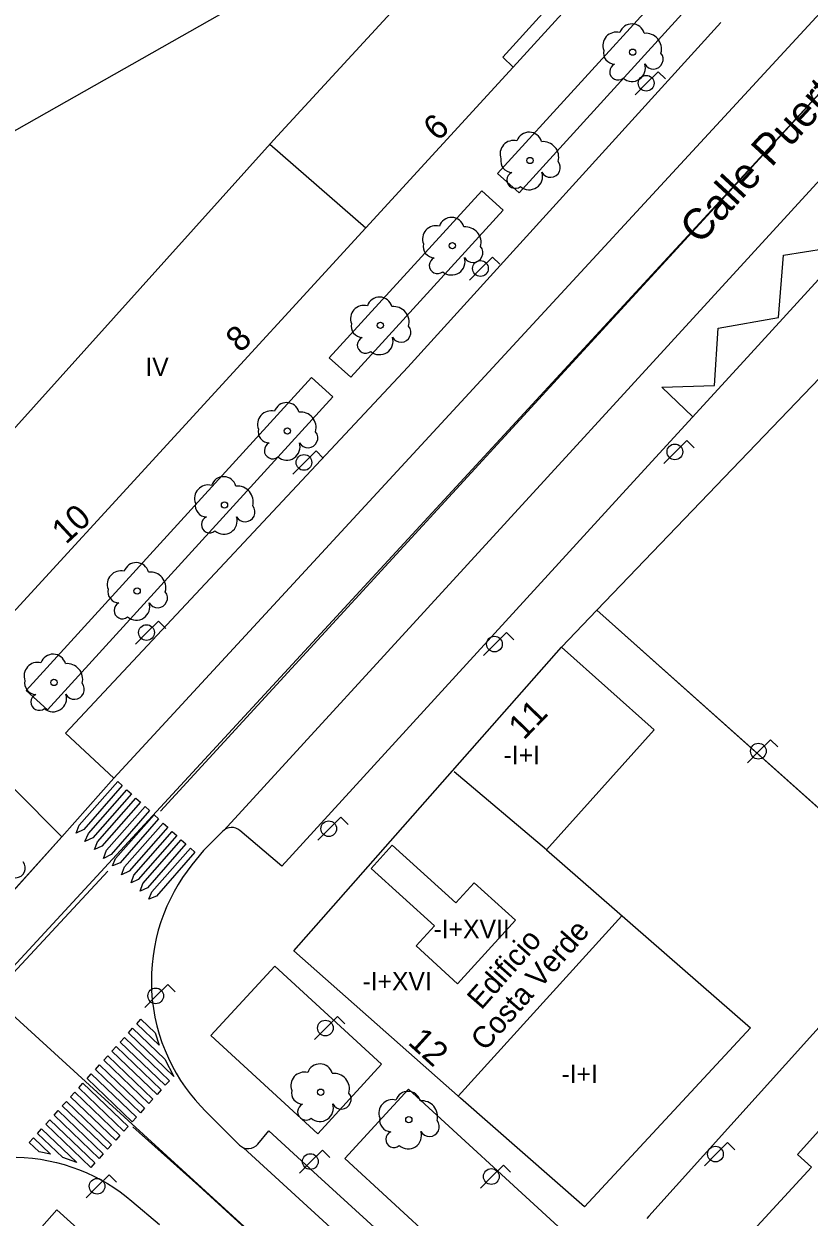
# Model space of a CAD drawing. Extents: x 282771 to 285132, y 4823109 to 4825496.
# Drawn here: x 283832.1 to 283895.8, y 4823389.4 to 4823486.3 of the extents above; entities that cross this region are included whole.
import ezdxf

# ---------------------------------------------------------------- set-up
doc = ezdxf.new("R2010")
doc.units = 0
for name, color, linetype in [('ACERA-BORDILLO', 7, 'Continuous'), ('ACERA-INTERIOR', 7, 'Continuous'), ('ARBOL', 7, 'Continuous'), ('CALLE-EJE', 7, 'Continuous'), ('CALLE-TEXTO', 7, 'Continuous'), ('CARGA_DESCARGA', 7, 'Continuous'), ('EDIFICIO', 7, 'Continuous'), ('FAROLA', 7, 'Continuous'), ('MEDIANERA', 7, 'Continuous'), ('NUM-LOCAL', 7, 'Continuous'), ('NUM-PORTAL', 7, 'Continuous'), ('PASO-PEATONES', 7, 'Continuous'), ('SENAL-VIARIA', 7, 'Continuous'), ('TXT-ALTURA-EDIFICIO', 7, 'Continuous'), ('TXT-EDIFICIOS', 7, 'Continuous'), ('ZONA-VERDE', 7, 'Continuous')]:
    doc.layers.add(name, color=color, linetype=linetype)

msp = doc.modelspace()

# ---------------------------------------------------------------- linework, layer by layer
at = {"layer": 'ACERA-BORDILLO'}
for points in [[(283785.072, 4823373.561), (283808.693, 4823399.156), (283812.812, 4823395.481), (283835.171, 4823420.3), (283839.411, 4823425.06), (283835.471, 4823428.73), (283863.261, 4823458.42), (283888.661, 4823486.42)], [(283908.741, 4823478.83), (283891.081, 4823459.53), (283880.401, 4823447.87), (283853.041, 4823417.91), (283849.616, 4823420.825), (283849.474, 4823420.926), (283849.307, 4823421.004), (283849.122, 4823421.051), (283848.928, 4823421.062), (283848.735, 4823421.036), (283848.555, 4823420.974), (283848.395, 4823420.882), (283848.261, 4823420.77), (283846.671, 4823419.18), (283845.739, 4823418.017), (283845.355, 4823417.516), (283844.986, 4823416.991), (283844.636, 4823416.444), (283844.306, 4823415.874), (283843.997, 4823415.282), (283843.712, 4823414.67), (283843.451, 4823414.039), (283843.218, 4823413.39), (283843.013, 4823412.726), (283842.838, 4823412.047), (283842.694, 4823411.356), (283842.582, 4823410.655), (283842.503, 4823409.947), (283842.457, 4823409.233), (283842.446, 4823408.516), (283842.469, 4823407.799), (283842.526, 4823407.083), (283842.618, 4823406.372), (283842.742, 4823405.667), (283842.9, 4823404.972), (283843.09, 4823404.288), (283843.31, 4823403.618), (283843.56, 4823402.963), (283843.838, 4823402.326), (283844.143, 4823401.707), (283844.472, 4823401.109), (283844.824, 4823400.533), (283845.197, 4823399.979), (283845.589, 4823399.45), (283845.998, 4823398.945), (283846.423, 4823398.465), (283846.86, 4823398.01), (283849.604, 4823395.278), (283849.752, 4823395.157), (283849.932, 4823395.061), (283850.137, 4823395.001), (283850.356, 4823394.988), (283850.572, 4823395.022), (283850.771, 4823395.099), (283850.941, 4823395.212), (283851.077, 4823395.346), (283851.981, 4823396.431), (283855.311, 4823393.371), (283891.081, 4823360.721)], [(283831.469, 4823394.303), (283832.135, 4823394.274), (283832.797, 4823394.215), (283833.456, 4823394.127), (283834.107, 4823394.011), (283834.751, 4823393.866), (283835.384, 4823393.694), (283836.006, 4823393.496), (283836.614, 4823393.273), (283837.208, 4823393.026), (283837.785, 4823392.755), (283838.346, 4823392.464), (283838.888, 4823392.152), (283839.411, 4823391.822), (283839.914, 4823391.475), (283839.914, 4823391.475), (283839.914, 4823391.475), (283839.914, 4823391.475), (283839.914, 4823391.475), (283840.396, 4823391.112), (283840.857, 4823390.736), (283843.105, 4823388.825)]]:
    msp.add_lwpolyline(points, dxfattribs=at)
at = {"layer": 'ACERA-INTERIOR'}
msp.add_line((283878.605, 4823438.71), (283875.731, 4823435.71), dxfattribs=at)
msp.add_lwpolyline([(283895.671, 4823509), (283891.081, 4823503.96), (283885.131, 4823497.43), (283871.801, 4823482.79)], dxfattribs=at)
at = {"layer": 'ARBOL'}
for centre in [(283881.511, 4823484), (283873.172, 4823475.208), (283866.875, 4823468.287), (283861.033, 4823461.82), (283853.488, 4823453.255), (283848.383, 4823447.242), (283841.292, 4823440.265), (283834.542, 4823432.834), (283856.191, 4823399.571), (283863.341, 4823397.341)]:
    msp.add_circle(centre, 0.255, dxfattribs=at)
for centre, radius, start, end in [((283880.181, 4823484.53), 1.097, 75.4318, 200.55608), ((283881.441, 4823485.26), 1.038, 15.64228, 161.38435), ((283882.571, 4823484.26), 1.272, 345.03273, 95.79925), ((283880.071, 4823483.96), 0.935, 168.59898, 268.13236), ((283883.181, 4823483.43), 0.797, 208.96246, 38.99103), ((283880.311, 4823482.41), 0.672, 113.73672, 309.4725), ((283881.451, 4823482.71), 1.086, 228.95447, 17.92796), ((283871.842, 4823475.738), 1.097, 75.4318, 200.55608), ((283873.102, 4823476.468), 1.038, 15.64228, 161.38435), ((283874.232, 4823475.468), 1.272, 345.03273, 95.79925), ((283871.732, 4823475.168), 0.935, 168.59898, 268.13236), ((283874.842, 4823474.638), 0.797, 208.96246, 38.99103), ((283871.972, 4823473.618), 0.672, 113.73672, 309.4725), ((283873.112, 4823473.918), 1.086, 228.95447, 17.92796), ((283866.805, 4823469.547), 1.038, 15.64228, 161.38435), ((283865.545, 4823468.817), 1.097, 75.4318, 200.55608), ((283867.935, 4823468.547), 1.272, 345.03273, 95.79925), ((283865.435, 4823468.247), 0.935, 168.59898, 268.13236), ((283868.545, 4823467.717), 0.797, 208.96246, 38.99103), ((283865.675, 4823466.697), 0.672, 113.73672, 309.4725), ((283866.815, 4823466.997), 1.086, 228.95447, 17.92796), ((283859.703, 4823462.35), 1.097, 75.4318, 200.55608), ((283860.963, 4823463.08), 1.038, 15.64228, 161.38435), ((283862.093, 4823462.08), 1.272, 345.03273, 95.79925), ((283859.593, 4823461.78), 0.935, 168.59898, 268.13236), ((283862.703, 4823461.25), 0.797, 208.96246, 38.99103), ((283859.833, 4823460.23), 0.672, 113.73672, 309.4725), ((283860.973, 4823460.53), 1.086, 228.95447, 17.92796), ((283853.418, 4823454.515), 1.038, 15.64228, 161.38435), ((283852.158, 4823453.785), 1.097, 75.4318, 200.55608), ((283854.548, 4823453.515), 1.272, 345.03273, 95.79925), ((283852.048, 4823453.215), 0.935, 168.59898, 268.13236), ((283855.158, 4823452.685), 0.797, 208.96246, 38.99103), ((283852.288, 4823451.665), 0.672, 113.73672, 309.4725), ((283853.428, 4823451.965), 1.086, 228.95447, 17.92796), ((283847.053, 4823447.772), 1.097, 75.4318, 200.55608), ((283848.313, 4823448.502), 1.038, 15.64228, 161.38435), ((283849.443, 4823447.502), 1.272, 345.03273, 95.79925), ((283846.943, 4823447.202), 0.935, 168.59898, 268.13236), ((283850.053, 4823446.672), 0.797, 208.96246, 38.99103), ((283847.183, 4823445.652), 0.672, 113.73672, 309.4725), ((283848.323, 4823445.952), 1.086, 228.95447, 17.92796), ((283839.962, 4823440.795), 1.097, 75.4318, 200.55608), ((283841.222, 4823441.525), 1.038, 15.64228, 161.38435), ((283842.352, 4823440.525), 1.272, 345.03273, 95.79925), ((283839.852, 4823440.225), 0.935, 168.59898, 268.13236), ((283842.962, 4823439.695), 0.797, 208.96246, 38.99103), ((283840.092, 4823438.675), 0.672, 113.73672, 309.4725), ((283841.232, 4823438.975), 1.086, 228.95447, 17.92796), ((283834.472, 4823434.094), 1.038, 15.64228, 161.38435), ((283833.212, 4823433.364), 1.097, 75.4318, 200.55608), ((283835.602, 4823433.094), 1.272, 345.03273, 95.79925), ((283833.102, 4823432.794), 0.935, 168.59898, 268.13236), ((283836.212, 4823432.264), 0.797, 208.96246, 38.99103), ((283833.342, 4823431.244), 0.672, 113.73672, 309.4725), ((283834.482, 4823431.544), 1.086, 228.95447, 17.92796), ((283831.429, 4823417.776), 0.797, 208.96246, 38.99103), ((283854.861, 4823400.101), 1.097, 75.4318, 200.55608), ((283856.121, 4823400.831), 1.038, 15.64228, 161.38435), ((283857.251, 4823399.831), 1.272, 345.03273, 95.79925), ((283854.751, 4823399.531), 0.935, 168.59898, 268.13236), ((283857.861, 4823399.001), 0.797, 208.96246, 38.99103), ((283863.271, 4823398.601), 1.038, 15.64228, 161.38435), ((283854.991, 4823397.981), 0.672, 113.73672, 309.4725), ((283856.131, 4823398.281), 1.086, 228.95447, 17.92796), ((283862.011, 4823397.871), 1.097, 75.4318, 200.55608), ((283864.401, 4823397.601), 1.272, 345.03273, 95.79925), ((283861.901, 4823397.301), 0.935, 168.59898, 268.13236), ((283862.141, 4823395.751), 0.672, 113.73672, 309.4725), ((283863.281, 4823396.051), 1.086, 228.95447, 17.92796), ((283865.011, 4823396.771), 0.797, 208.96246, 38.99103)]:
    msp.add_arc(centre, radius, start, end, dxfattribs=at)
at = {"layer": 'CALLE-EJE'}
for points in [[(283915.67, 4823562.869), (283930.947, 4823535.839), (283932.069, 4823532.819), (283932.63, 4823529.669), (283932.738, 4823527.699), (283932.738, 4823525.68), (283932.366, 4823523.289), (283931.782, 4823521.004), (283930.796, 4823518.998), (283923.914, 4823510.21), (283829.231, 4823407.601)], [(283918.081, 4823326.402), (283829.231, 4823407.601)]]:
    msp.add_lwpolyline(points, dxfattribs=at)
at = {"layer": 'CARGA_DESCARGA'}
msp.add_lwpolyline([(283886.377, 4823454.394), (283883.876, 4823456.809), (283888.139, 4823456.939), (283888.44, 4823461.604), (283893.338, 4823462.459), (283893.736, 4823467.519), (283898.863, 4823468.329), (283899.318, 4823473.401), (283901.842, 4823471.291)], dxfattribs=at)
at = {"layer": 'EDIFICIO'}
for points in [[(283832.841, 4823490.48), (283870.601, 4823511.93), (283880.631, 4823494.27), (283870.961, 4823483.59), (283871.801, 4823482.79), (283859.851, 4823469.75), (283829.381, 4823436.52), (283822.051, 4823443.15), (283852.351, 4823476.86), (283871.091, 4823497.24), (283869.751, 4823499.39), (283829.221, 4823476.43), (283823.881, 4823485.39), (283832.841, 4823490.48)], [(283875.731, 4823435.71), (283883.251, 4823428.98), (283874.501, 4823419.25), (283891.061, 4823404.801), (283877.591, 4823390.271), (283867.541, 4823399.091), (283854.011, 4823411.051), (283875.731, 4823435.71)]]:
    msp.add_lwpolyline(points, dxfattribs=at)
at = {"layer": 'FAROLA'}
for p, q in [((283883.58, 4823482.414), (283882.64, 4823481.484)), ((283884.17, 4823481.824), (283883.58, 4823482.414)), ((283882.64, 4823481.484), (283881.71, 4823480.544)), ((283870.134, 4823467.37), (283869.194, 4823466.44)), ((283870.724, 4823466.78), (283870.134, 4823467.37)), ((283869.194, 4823466.44), (283868.264, 4823465.5)), ((283855.81, 4823451.625), (283854.87, 4823450.695)), ((283856.4, 4823451.035), (283855.81, 4823451.625)), ((283884.971, 4823451.553), (283884.041, 4823450.613)), ((283885.911, 4823452.483), (283884.971, 4823451.553)), ((283886.501, 4823451.893), (283885.911, 4823452.483)), ((283854.87, 4823450.695), (283853.94, 4823449.755)), ((283843.034, 4823437.814), (283842.094, 4823436.884)), ((283843.624, 4823437.224), (283843.034, 4823437.814)), ((283842.094, 4823436.884), (283841.164, 4823435.944)), ((283871.269, 4823436.882), (283870.329, 4823435.952)), ((283871.859, 4823436.292), (283871.269, 4823436.882)), ((283870.329, 4823435.952), (283869.399, 4823435.012)), ((283892.686, 4823428.186), (283891.746, 4823427.256)), ((283893.276, 4823427.596), (283892.686, 4823428.186)), ((283891.746, 4823427.256), (283890.816, 4823426.316)), ((283857.822, 4823421.892), (283856.882, 4823420.962)), ((283858.412, 4823421.302), (283857.822, 4823421.892)), ((283856.882, 4823420.962), (283855.952, 4823420.022)), ((283843.781, 4823408.321), (283842.841, 4823407.391)), ((283844.371, 4823407.731), (283843.781, 4823408.321)), ((283842.841, 4823407.391), (283841.911, 4823406.451)), ((283857.548, 4823405.709), (283856.608, 4823404.779)), ((283858.138, 4823405.119), (283857.548, 4823405.709)), ((283856.608, 4823404.779), (283855.678, 4823403.839)), ((283889.202, 4823395.477), (283888.262, 4823394.547)), ((283889.792, 4823394.887), (283889.202, 4823395.477)), ((283856.329, 4823394.873), (283855.389, 4823393.943)), ((283856.919, 4823394.283), (283856.329, 4823394.873)), ((283888.262, 4823394.547), (283887.332, 4823393.607)), ((283855.389, 4823393.943), (283854.459, 4823393.003)), ((283871.014, 4823393.657), (283870.074, 4823392.727)), ((283871.604, 4823393.067), (283871.014, 4823393.657)), ((283839.025, 4823392.867), (283838.085, 4823391.937)), ((283839.615, 4823392.277), (283839.025, 4823392.867)), ((283870.074, 4823392.727), (283869.144, 4823391.787)), ((283838.085, 4823391.937), (283837.155, 4823390.997))]:
    msp.add_line(p, q, dxfattribs=at)
for centre, radius in [((283882.6, 4823481.484), 0.637), ((283869.154, 4823466.44), 0.637), ((283884.931, 4823451.553), 0.637), ((283854.83, 4823450.695), 0.637), ((283842.054, 4823436.884), 0.638), ((283870.289, 4823435.952), 0.637), ((283891.706, 4823427.256), 0.638), ((283856.842, 4823420.962), 0.637), ((283842.801, 4823407.391), 0.637), ((283856.568, 4823404.779), 0.637), ((283855.349, 4823393.943), 0.637), ((283888.222, 4823394.547), 0.638), ((283838.045, 4823391.937), 0.637), ((283870.034, 4823392.727), 0.637)]:
    msp.add_circle(centre, radius, dxfattribs=at)
at = {"layer": 'MEDIANERA'}
for points in [[(283852.051, 4823476.53), (283859.851, 4823469.75)], [(283874.501, 4823419.25), (283867.021, 4823425.58)], [(283868.651, 4823416.581), (283867.161, 4823414.941), (283861.991, 4823419.63), (283860.281, 4823417.74), (283865.421, 4823413.081), (283863.931, 4823411.441), (283867.301, 4823408.381), (283872.001, 4823413.541), (283868.651, 4823416.581)], [(283880.631, 4823413.891), (283867.331, 4823399.261)]]:
    msp.add_lwpolyline(points, dxfattribs=at)
at = {"layer": 'PASO-PEATONES'}
for points in [[(283836.34, 4823420.603), (283836.598, 4823421.239), (283839.72, 4823424.8), (283840.091, 4823424.464), (283836.967, 4823420.9)], [(283837.054, 4823419.928), (283837.335, 4823420.562), (283840.457, 4823424.123), (283840.827, 4823423.787), (283837.703, 4823420.223)], [(283837.846, 4823419.265), (283838.071, 4823419.885), (283841.195, 4823423.449), (283841.564, 4823423.11), (283838.44, 4823419.546)], [(283838.56, 4823418.551), (283838.808, 4823419.208), (283841.932, 4823422.772), (283842.3, 4823422.434), (283839.176, 4823418.87)], [(283839.288, 4823417.954), (283839.544, 4823418.531), (283842.668, 4823422.095), (283843.037, 4823421.757), (283839.913, 4823418.193)], [(283840.015, 4823417.227), (283840.281, 4823417.855), (283843.405, 4823421.418), (283843.773, 4823421.08), (283840.649, 4823417.516)], [(283840.807, 4823416.565), (283841.017, 4823417.178), (283844.141, 4823420.742), (283844.51, 4823420.403), (283841.386, 4823416.839)], [(283841.547, 4823415.902), (283841.754, 4823416.501), (283844.878, 4823420.065), (283845.246, 4823419.726), (283842.122, 4823416.163)], [(283842.248, 4823415.253), (283842.491, 4823415.824), (283845.615, 4823419.388), (283845.983, 4823419.05), (283842.859, 4823415.486)], [(283843.074, 4823403.389), (283841.265, 4823405.127), (283841.601, 4823405.498), (283842.744, 4823404.399)], [(283844.279, 4823400.845), (283840.593, 4823404.386), (283840.929, 4823404.757), (283843.547, 4823402.242)], [(283842.909, 4823399.387), (283839.25, 4823402.902), (283839.586, 4823403.273), (283843.245, 4823399.758)], [(283843.581, 4823400.129), (283839.922, 4823403.644), (283840.258, 4823404.015), (283843.916, 4823400.5)], [(283842.238, 4823398.646), (283838.579, 4823402.161), (283838.915, 4823402.532), (283842.573, 4823399.017)], [(283841.566, 4823397.904), (283837.907, 4823401.419), (283838.243, 4823401.79), (283841.902, 4823398.275)], [(283840.223, 4823396.421), (283836.564, 4823399.936), (283836.9, 4823400.307), (283840.559, 4823396.792)], [(283840.895, 4823397.163), (283837.236, 4823400.678), (283837.572, 4823401.049), (283841.23, 4823397.534)], [(283839.552, 4823395.68), (283835.893, 4823399.195), (283836.229, 4823399.565), (283839.887, 4823396.05)], [(283838.88, 4823394.938), (283835.221, 4823398.453), (283835.557, 4823398.824), (283839.216, 4823395.309)], [(283837.537, 4823393.455), (283833.878, 4823396.97), (283834.214, 4823397.341), (283837.873, 4823393.826)], [(283838.209, 4823394.196), (283834.55, 4823397.712), (283834.886, 4823398.082), (283838.544, 4823394.567)], [(283835.256, 4823394.26), (283833.207, 4823396.228), (283833.543, 4823396.599), (283836.394, 4823393.859)], [(283833.336, 4823394.718), (283832.535, 4823395.487), (283832.871, 4823395.857), (283834.251, 4823394.532)]]:
    msp.add_lwpolyline(points, close=True, dxfattribs=at)
at = {"layer": 'SENAL-VIARIA'}
for points in [[(283839.411, 4823425.06), (283920.682, 4823513.209)], [(283843.193, 4823422.375), (283923.682, 4823510.119)], [(283848.328, 4823420.826), (283927.419, 4823507.226)], [(283829.811, 4823407.712), (283838.929, 4823417.508)], [(283846.291, 4823391.979), (283840.943, 4823396.759)], [(283849.932, 4823395.061), (283905.341, 4823344.251)], [(283846.291, 4823391.979), (283899.822, 4823342.997)]]:
    msp.add_lwpolyline(points, dxfattribs=at)
at = {"layer": 'ZONA-VERDE'}
for p, q in [((283870.541, 4823474.162), (283883.752, 4823488.658)), ((283885.492, 4823487.088), (283872.281, 4823472.592)), ((283872.281, 4823472.592), (283870.541, 4823474.162)), ((283856.883, 4823459.176), (283869.255, 4823472.751)), ((283869.255, 4823472.751), (283870.995, 4823471.18)), ((283870.995, 4823471.18), (283858.624, 4823457.606)), ((283902.441, 4823463.59), (283878.605, 4823438.71)), ((283902.441, 4823463.59), (283878.605, 4823438.71)), ((283858.624, 4823457.606), (283856.883, 4823459.176)), ((283832.281, 4823432.18), (283855.44, 4823457.591)), ((283855.44, 4823457.591), (283857.18, 4823456.021)), ((283857.18, 4823456.021), (283834.021, 4823430.61)), ((283834.021, 4823430.61), (283832.281, 4823432.18)), ((283847.279, 4823404.18), (283852.46, 4823409.81)), ((283852.46, 4823409.81), (283861.13, 4823401.834)), ((283855.97, 4823396.189), (283847.279, 4823404.18)), ((283861.13, 4823401.834), (283855.97, 4823396.189)), ((283858.153, 4823394.181), (283863.312, 4823399.826)), ((283863.312, 4823399.826), (283875.449, 4823388.66)), ((283870.279, 4823383.03), (283858.153, 4823394.181)), ((283829.369, 4823383.96), (283834.779, 4823390.01)), ((283834.779, 4823390.01), (283842.449, 4823383.15))]:
    msp.add_line(p, q, dxfattribs=at)
for points in [[(283878.605, 4823438.71), (283907.158, 4823413.192), (283917.81, 4823424)], [(283878.605, 4823438.71), (283904.631, 4823415.451), (283907.158, 4823413.192)], [(283829.334, 4823413.821), (283835.171, 4823420.3), (283831.346, 4823424.174), (283825.262, 4823417.455), (283829.334, 4823413.821)], [(283898.329, 4823406.741), (283882.813, 4823389.514), (283882.641, 4823389.306)], [(283885.991, 4823382.591), (283896.011, 4823393.491), (283894.871, 4823394.501), (283903.941, 4823404.591)]]:
    msp.add_lwpolyline(points, dxfattribs=at)

# ---------------------------------------------------------------- texts
at = {"layer": 'CALLE-TEXTO'}
msp.add_text('Calle Puerto de Somiedo', height=2.5, rotation=47.30076, dxfattribs=at).set_placement((283886.954, 4823468.312))
at = {"layer": 'NUM-LOCAL'}
msp.add_text('11', height=2, rotation=46.03004, dxfattribs=at).set_placement((283872.665, 4823428.096))
at = {"layer": 'NUM-PORTAL'}
for s, rotation, p in [('6', 42.86127, (283865.667, 4823476.703)), ('8', 42.86127, (283849.64, 4823459.541)), ('10', 42.86127, (283835.511, 4823443.985)), ('12', 317.68004, (283863.187, 4823403.527))]:
    msp.add_text(s, height=2, rotation=rotation, dxfattribs=at).set_placement(p)
at = {"layer": 'TXT-ALTURA-EDIFICIO'}
for s, p in [('IV', (283841.962, 4823457.71)), ('-I+I', (283871.027, 4823426.2)), ('-I+XVII', (283865.344, 4823412.071)), ('-I+XVI', (283859.574, 4823407.831)), ('-I+I', (283875.727, 4823400.311))]:
    msp.add_text(s, height=1.5, rotation=0.00004, dxfattribs=at).set_placement(p)
at = {"layer": 'TXT-EDIFICIOS'}
for s, p in [('Costa Verde', (283869.521, 4823402.833)), ('Edificio ', (283869.223, 4823406.188))]:
    msp.add_text(s, height=1.75, rotation=48.69101, dxfattribs=at).set_placement(p)

doc.saveas('drawing.dxf')
